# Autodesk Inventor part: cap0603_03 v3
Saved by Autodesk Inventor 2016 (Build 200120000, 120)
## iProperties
Created: 2016-09
Part Number: cap0603_03 v3
Material: Generic
Document SubType Name: Modeling
Designer: Administrator
Appearance: Generic
Author: Administrator
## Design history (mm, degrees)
feature "Body6"
feature "Body8"
feature "Body18"
body "Solid1"
body "Solid2"
body "Solid3"
